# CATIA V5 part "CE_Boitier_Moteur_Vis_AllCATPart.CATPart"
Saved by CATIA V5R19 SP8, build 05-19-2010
Part number: CE4_Boitier_Moteur_Vis_AllCATPart
Bounding box of the stored display mesh (mm): x -120.658 to -0.5, y 81.911 to 196.296, z 10.207 to 159.922
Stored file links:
  D:\Documents\1_Travail\1 - ac-limoges.fr\ac-limoges.fr\Emmanuel Maynard - STI2D_Turgot\2 -2I2D\1_SEQUENCE_ Tapis_de_course\3- Spécificités\Spé_ITEC\3-Pente\Tapis_TC520B_Pente\CE_Boitier_Moteur_Vis_AllCATPart.CATPart
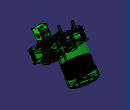
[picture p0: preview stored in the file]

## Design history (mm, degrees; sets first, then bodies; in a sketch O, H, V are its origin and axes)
AxisSystem1: origin (0, 0, 0), X (1, 0, 0), Y (0, 1, 0), Z (0, 0, 1)
AxisSystem2: origin (-33, 130.9839, 88.3632), X (0, -0.5214, 0.8533), Y (0, 0.8533, 0.5214), Z (-1, 0, 0)
Body1 (main body)
  Point1: type Center, Curve edge [face of Solid1 | face of Solid1]
  Line1: type PtPt, FirstPoint {point type Center, Curve edge [face of Solid1 | face of Solid1]}, SecondPoint {point type Center, Curve edge [face of Solid1 | face of Solid1]}
Body2 "Corps Inf de BMV.1"
  Solid1: solid without history
  Body3 "Corps Inf de BMV.1\\Axes rous"
    Solid2 "Solide.1": solid without history
  Add1 "Corps Inf de BMV.1\\Axes rous": tool Body3
  Body4 "Corps Inf de BMV.1\\bague"
    Solid3 "Solide.1": solid without history
  Add2 "Corps Inf de BMV.1\\bague": tool Body4
Body5 "Flasque_ButéeAiguilles.1\\Corps principal"
  Solid4 "Solide.1": solid without history
Body6 "l7-axk1226_1.1"
  Solid5 "Solide.1": solid without history
  Body7 "l7-axk1226_1.1\\l7-axk1226_2"
    Solid6 "Solide.1": solid without history
  Add3 "l7-axk1226_1.1\\l7-axk1226_2": tool Body7
  Body8 "l7-axk1226_1.1\\l7-axk1226_3"
    Solid7 "Solide.1": solid without history
  Add4 "l7-axk1226_1.1\\l7-axk1226_3": tool Body8
  Body9 "l7-axk1226_1.1\\l7-axk1226_4"
    Solid8 "Solide.1": solid without history
  Add5 "l7-axk1226_1.1\\l7-axk1226_4": tool Body9
  Body10 "l7-axk1226_1.1\\l7-axk1226_5"
    Solid9 "Solide.1": solid without history
  Add6 "l7-axk1226_1.1\\l7-axk1226_5": tool Body10
  Body11 "l7-axk1226_1.1\\l7-axk1226_6"
    Solid10 "Solide.1": solid without history
  Add7 "l7-axk1226_1.1\\l7-axk1226_6": tool Body11
  Body12 "l7-axk1226_1.1\\l7-axk1226_7"
    Solid11 "Solide.1": solid without history
  Add8 "l7-axk1226_1.1\\l7-axk1226_7": tool Body12
  Body13 "l7-axk1226_1.1\\l7-axk1226_8"
    Solid12 "Solide.1": solid without history
  Add9 "l7-axk1226_1.1\\l7-axk1226_8": tool Body13
  Body14 "l7-axk1226_1.1\\l7-axk1226_9"
    Solid13 "Solide.1": solid without history
  Add10 "l7-axk1226_1.1\\l7-axk1226_9": tool Body14
Body15 "Cale_Butee_Aiguilles.1\\Corps principal"
  Solid14 "Solide.1": solid without history
Body16 "Flasque_ButéeAiguilles.2\\Corps principal"
  Solid15 "Solide.1": solid without history
Body17 "l7-axk1226_1.2"
  Solid16 "Solide.1": solid without history
  Body18 "l7-axk1226_1.2\\l7-axk1226_2"
    Solid17 "Solide.1": solid without history
  Add11 "l7-axk1226_1.2\\l7-axk1226_2": tool Body18
  Body19 "l7-axk1226_1.2\\l7-axk1226_3"
    Solid18 "Solide.1": solid without history
  Add12 "l7-axk1226_1.2\\l7-axk1226_3": tool Body19
  Body20 "l7-axk1226_1.2\\l7-axk1226_4"
    Solid19 "Solide.1": solid without history
  Add13 "l7-axk1226_1.2\\l7-axk1226_4": tool Body20
  Body21 "l7-axk1226_1.2\\l7-axk1226_5"
    Solid20 "Solide.1": solid without history
  Add14 "l7-axk1226_1.2\\l7-axk1226_5": tool Body21
  Body22 "l7-axk1226_1.2\\l7-axk1226_6"
    Solid21 "Solide.1": solid without history
  Add15 "l7-axk1226_1.2\\l7-axk1226_6": tool Body22
  Body23 "l7-axk1226_1.2\\l7-axk1226_7"
    Solid22 "Solide.1": solid without history
  Add16 "l7-axk1226_1.2\\l7-axk1226_7": tool Body23
  Body24 "l7-axk1226_1.2\\l7-axk1226_8"
    Solid23 "Solide.1": solid without history
  Add17 "l7-axk1226_1.2\\l7-axk1226_8": tool Body24
  Body25 "l7-axk1226_1.2\\l7-axk1226_9"
    Solid24 "Solide.1": solid without history
  Add18 "l7-axk1226_1.2\\l7-axk1226_9": tool Body25
Body26 "Cloche_Moteur_Vis.1\\Corps principal"
  Solid25 "Solide.1": solid without history
Body27 "Stator_Moteur_Vis.2\\Corps principal"
  Solid26 "Solide.1": solid without history
Body28 "Corps sup BMV.1\\Corps principal"
  Solid27 "Solide.1": solid without history
Body29 "Silemblocs-vérin.1\\Corps principal"
  Solid28 "Solide.1": solid without history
